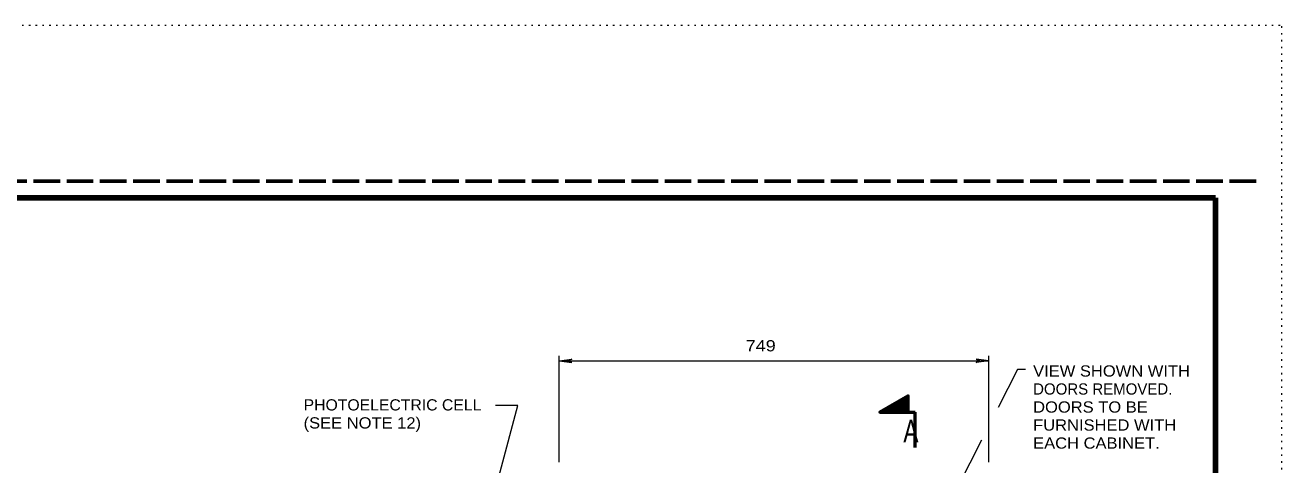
# Model space of a CAD drawing. Extents: x 312583 to 312854, y 144419 to 144597.
# Drawn here: x 312768.4 to 312853.5, y 144567 to 144596.8 of the extents above; entities that cross this region are included whole.
import ezdxf
from ezdxf.enums import TextEntityAlignment as Align

# ---------------------------------------------------------------- set-up
doc = ezdxf.new("R2010")
doc.units = 0
doc.header["$LTSCALE"] = 0.3
doc.linetypes.add('DOTTED', pattern=[1.5, 0.3, -1.2])
doc.linetypes.add('LONG_DASHED', pattern=[7.5, 6, -1.5])
doc.layers.add('1', color=7, linetype='Continuous', lineweight=25)
doc.layers.add('2', color=7, linetype='Continuous', lineweight=13)

msp = doc.modelspace()

# ---------------------------------------------------------------- linework, layer by layer
at = {"layer": '1', "linetype": 'DOTTED', "lineweight": 13}
msp.add_line((312601.2, 144596.7846), (312853.5, 144596.7846), dxfattribs=at)
at = {"layer": '1', "linetype": 'LONG_DASHED', "lineweight": 60}
msp.add_line((312851.75, 144586.2246), (312583.526, 144586.2246), dxfattribs=at)
at = {"layer": '1', "lineweight": 158}
for p in [(312616.5, 144585.0846), (312849, 144423.1446)]:
    msp.add_line(p, (312849, 144585.0846), dxfattribs=at)
at = {"layer": '1', "lineweight": 35}
for p, q in [((312828.185, 144571.6096), (312828.1467, 144571.6633)), ((312828.185, 144571.6556), (312828.1697, 144571.671)), ((312826.782, 144570.5746), (312826.6517, 144570.8046)), ((312826.8127, 144570.5746), (312826.6747, 144570.8123)), ((312826.8433, 144570.5746), (312826.6977, 144570.8276)), ((312826.8663, 144570.5746), (312826.713, 144570.8353)), ((312826.897, 144570.5746), (312826.7437, 144570.8506)), ((312826.92, 144570.5746), (312826.759, 144570.8583)), ((312826.9507, 144570.5746), (312826.782, 144570.8736)), ((312826.9813, 144570.5746), (312826.805, 144570.8813)), ((312827.0043, 144570.5746), (312826.8203, 144570.8966)), ((312827.035, 144570.5746), (312826.8433, 144570.9043)), ((312827.058, 144570.5746), (312826.8663, 144570.9196)), ((312827.0887, 144570.5746), (312826.8817, 144570.935)), ((312827.1117, 144570.5746), (312826.9047, 144570.9426)), ((312827.1423, 144570.5746), (312826.9277, 144570.958)), ((312827.173, 144570.5746), (312826.943, 144570.9733)), ((312827.2037, 144570.5746), (312826.966, 144570.981)), ((312827.2267, 144570.5746), (312826.989, 144570.9963)), ((312827.2497, 144570.5746), (312827.012, 144571.004)), ((312827.2803, 144570.5746), (312827.0273, 144571.0193)), ((312827.311, 144570.5746), (312827.0503, 144571.027)), ((312827.334, 144570.5746), (312827.0733, 144571.0423)), ((312827.3647, 144570.5746), (312827.0887, 144571.05)), ((312827.3953, 144570.5746), (312827.1117, 144571.0653)), ((312827.4183, 144570.5746), (312827.1347, 144571.073)), ((312827.449, 144570.5746), (312827.15, 144571.0883)), ((312827.4797, 144570.5746), (312827.173, 144571.096)), ((312827.5027, 144570.5746), (312827.196, 144571.1113)), ((312827.5333, 144570.5823), (312827.2113, 144571.1266)), ((312827.5563, 144570.5746), (312827.242, 144571.1343)), ((312827.587, 144570.5746), (312827.2573, 144571.1496)), ((312827.61, 144570.5746), (312827.2803, 144571.1573)), ((312827.6407, 144570.5746), (312827.3033, 144571.1726)), ((312827.6713, 144570.5746), (312827.3187, 144571.1803)), ((312827.702, 144570.5746), (312827.3417, 144571.1956)), ((312827.725, 144570.5746), (312827.3647, 144571.2033)), ((312827.748, 144570.5746), (312827.38, 144571.2186)), ((312827.7787, 144570.5823), (312827.403, 144571.2263)), ((312827.8093, 144570.5746), (312827.426, 144571.2416)), ((312827.8323, 144570.5746), (312827.4413, 144571.2493)), ((312827.863, 144570.5746), (312827.4643, 144571.2646)), ((312827.8937, 144570.5746), (312827.4873, 144571.28)), ((312827.9167, 144570.5746), (312827.5103, 144571.2876)), ((312827.9473, 144570.5746), (312827.5257, 144571.303)), ((312827.978, 144570.5746), (312827.5487, 144571.3183)), ((312828.001, 144570.5823), (312827.5717, 144571.326)), ((312828.0317, 144570.5823), (312827.587, 144571.3413)), ((312828.0547, 144570.5746), (312827.61, 144571.349)), ((312828.0853, 144570.5746), (312827.633, 144571.3643)), ((312828.1083, 144570.5746), (312827.6483, 144571.372)), ((312828.139, 144570.5746), (312827.6713, 144571.3873)), ((312828.1697, 144570.5746), (312827.6943, 144571.395)), ((312828.185, 144570.5976), (312827.7097, 144571.4103)), ((312828.185, 144570.6513), (312827.7403, 144571.418)), ((312828.185, 144570.6896), (312827.7557, 144571.4333)), ((312828.185, 144570.7433), (312827.7787, 144571.441)), ((312828.185, 144570.7893), (312827.8017, 144571.4563)), ((312828.185, 144570.8353), (312827.817, 144571.4716)), ((312828.185, 144570.8813), (312827.84, 144571.4793)), ((312828.185, 144570.935), (312827.863, 144571.4946)), ((312828.185, 144570.981), (312827.8783, 144571.51)), ((312828.185, 144571.027), (312827.9013, 144571.5176)), ((312828.185, 144571.0806), (312827.9167, 144571.533)), ((312828.185, 144571.1266), (312827.9397, 144571.5406)), ((312828.185, 144571.1726), (312827.9627, 144571.556)), ((312828.185, 144571.2263), (312827.978, 144571.5636)), ((312828.185, 144571.2723), (312828.0087, 144571.579)), ((312828.185, 144571.3183), (312828.024, 144571.5866)), ((312828.185, 144571.3643), (312828.047, 144571.602)), ((312828.185, 144571.418), (312828.07, 144571.6096)), ((312828.185, 144571.4563), (312828.0853, 144571.625)), ((312828.185, 144571.51), (312828.1083, 144571.6326)), ((312828.185, 144571.556), (312828.1313, 144571.648)), ((312826.2837, 144570.5746), (312826.2837, 144570.59)), ((312826.3143, 144570.5746), (312826.3067, 144570.5976)), ((312826.345, 144570.5746), (312826.322, 144570.613)), ((312826.368, 144570.5746), (312826.345, 144570.6206)), ((312826.3987, 144570.5746), (312826.368, 144570.636)), ((312826.4217, 144570.5746), (312826.3833, 144570.6436)), ((312826.4523, 144570.5746), (312826.4063, 144570.659)), ((312826.483, 144570.5746), (312826.4293, 144570.6666)), ((312826.5137, 144570.5746), (312826.4447, 144570.682)), ((312826.5367, 144570.5746), (312826.4677, 144570.6896)), ((312826.5597, 144570.5746), (312826.4907, 144570.705)), ((312826.5903, 144570.5746), (312826.5137, 144570.7126)), ((312826.6133, 144570.5746), (312826.529, 144570.728)), ((312826.644, 144570.5746), (312826.552, 144570.7433)), ((312826.6747, 144570.5746), (312826.575, 144570.751)), ((312826.7053, 144570.5746), (312826.5903, 144570.7663)), ((312826.7283, 144570.5746), (312826.6133, 144570.7816)), ((312826.759, 144570.5746), (312826.6363, 144570.7893))]:
    msp.add_line(p, q, dxfattribs=at)
at = {"layer": '1', "lineweight": 53}
for p in [(312828.185, 144570.5746), (312828.6603, 144568.1826)]:
    msp.add_line(p, (312828.6603, 144570.5746), dxfattribs=at)
at = {"layer": '1', "linetype": 'DOTTED', "lineweight": 13}
msp.add_lwpolyline([(312601.2, 144418.5846), (312853.5, 144418.5846), (312853.5, 144596.7846)], dxfattribs=at)
at = {"layer": '1', "lineweight": 53}
msp.add_lwpolyline([(312828.185, 144570.5746), (312828.185, 144571.6863), (312826.2683, 144570.5746)], close=True, dxfattribs=at)
at = {"layer": '2'}
for p, q in [((312804.5487, 144567.209), (312804.5487, 144574.408)), ((312833.659, 144567.209), (312833.659, 144574.408)), ((312804.5487, 144574.0553), (312805.415, 144574.1626)), ((312804.5487, 144574.0553), (312805.415, 144573.948)), ((312804.5487, 144574.0553), (312833.659, 144574.0553)), ((312805.415, 144574.1626), (312805.139, 144574.0553)), ((312805.415, 144573.948), (312805.139, 144574.0553)), ((312832.7927, 144574.1626), (312833.0687, 144574.0553)), ((312833.659, 144574.0553), (312832.7927, 144574.1626)), ((312832.7927, 144573.948), (312833.0687, 144574.0553)), ((312833.659, 144574.0553), (312832.7927, 144573.948)), ((312833.1683, 144568.6963), (312831.5737, 144565.5683))]:
    msp.add_line(p, q, dxfattribs=at)
for points in [[(312836.143, 144573.4803), (312835.6063, 144573.4803), (312834.2953, 144570.9043)], [(312799.274, 144561.712), (312801.758, 144571.0423), (312800.24, 144571.0423)]]:
    msp.add_lwpolyline(points, dxfattribs=at)

# ---------------------------------------------------------------- texts
at = {"layer": '1', "width": 0.75}
msp.add_text('A', height=1.533, dxfattribs=at).set_placement((312828.3767, 144568.5353), align=Align.CENTER)
at = {"layer": '2'}
for s, width, p in [('749 ', 1.2, (312817.186, 144574.6995)), ('VIEW SHOWN WITH ', 1.1, (312836.6548, 144572.9933)), ('PHOTOELECTRIC CELL', 1.05, (312787.2475, 144570.6978)), ('DOORS TO BE', 1.1, (312836.6548, 144570.5533)), ('(SEE NOTE 12)', 1.1, (312787.2475, 144569.4778)), ('FURNISHED WITH ', 1.1, (312836.6548, 144569.3333)), ('EACH CABINET.', 1.1, (312836.6548, 144568.1133))]:
    msp.add_text(s, height=0.76, dxfattribs=dict(at, width=width)).set_placement(p)
msp.add_text('DOORS REMOVED.', height=0.76, dxfattribs=at).set_placement((312836.6548, 144571.7733))

doc.saveas('drawing.dxf')
